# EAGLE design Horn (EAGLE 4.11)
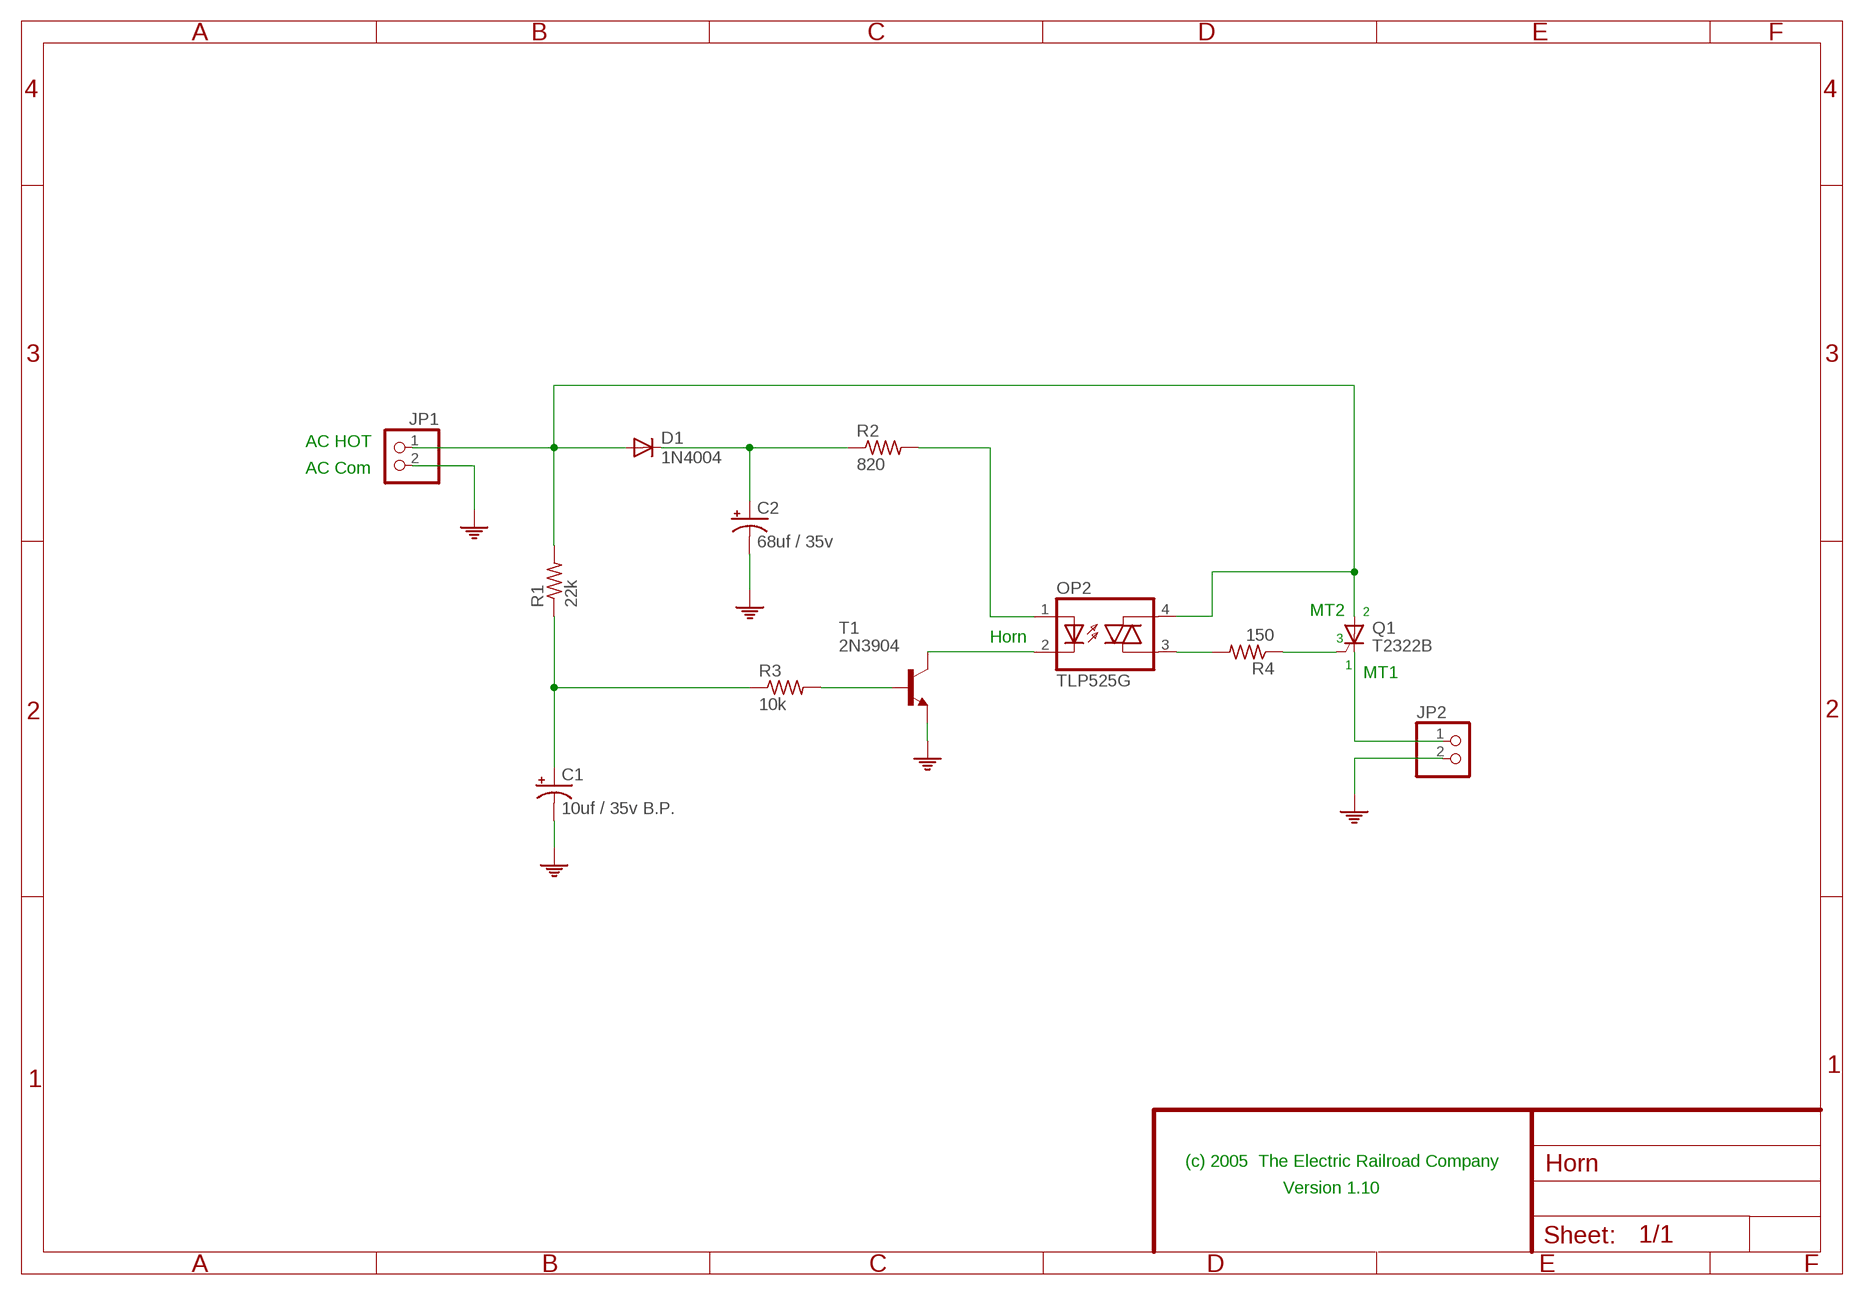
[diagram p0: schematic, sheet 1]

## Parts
C1  10uf / 35v B.P.  CPOL-USE2.5-6  [E2,5-6]
C2  68uf / 35v  CPOL-USE2.5-7  [E2,5-7]
D1  1N4004  DIODE-D-2.5  [D-2.5]
JP1  PINHD-1X2  [1X02]
JP2  PINHD-1X2  [1X02]
OP2  TLP525G  IL420  [DIL04]
Q1  T2322B  BT148  [SOT82S]
R1  22k  R-US_0204/2V  [0204V]
R2  820  R-US_0204/2V  [0204V]
R3  10k  R-US_0204/2V  [0204V]
R4  150  R-US_0204/2V  [0204V]
T1  2N3904  [TO92]

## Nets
N$2 [P24]: D1.A JP1.1 OP2.4(A2) Q1.A R1.2
N$3: OP2.1(A) R2.2
N$7: C1.+ R1.1 R3.1
N$8: R3.2 T1.2(B)
N$9: Q1.G R4.1
N$10: OP2.2(C) T1.1(C)
N$14: C2.+ D1.C R2.1
N$17: OP2.3(A1) R4.2
N$20 [P24]: JP2.1 Q1.C
PE [P24]: C1.- C2.- JP1.2 JP2.2 T1.3(E)

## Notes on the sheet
- AC HOT
- AC Com
- MT2 | 2
- Horn | 3
- 1
- MT1
- (c) 2005  The Electric Railroad Company
- Version 1.10

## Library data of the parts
C1 C2 = rcl:CPOL-US: POLARIZED CAPACITOR, American symbol
D1 = diode:DIODE-: DIODE
JP1 JP2 = pinhead:PINHD-1X2: PIN HEADER
OP2 = optocoupler-jz:IL420: SIEMENS OPTO COUPLER
Q1 = triac:BT148: THYRISTOR
R1-R4 = rcl:R-US_: RESISTOR, American symbol
T1 = transistor:2N3904: NPN TRANSISTOR

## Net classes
1 P24: width 0.61 mm, drill 0.508 mm, clearance 0.61 mm

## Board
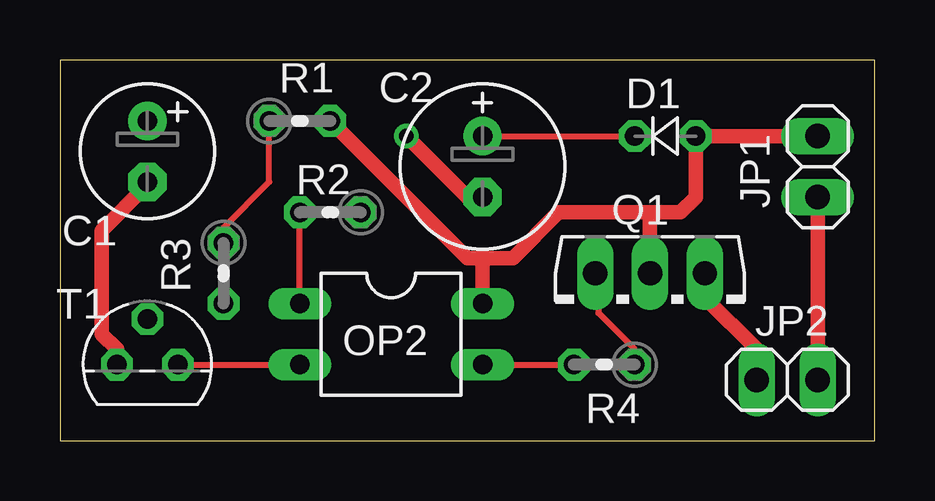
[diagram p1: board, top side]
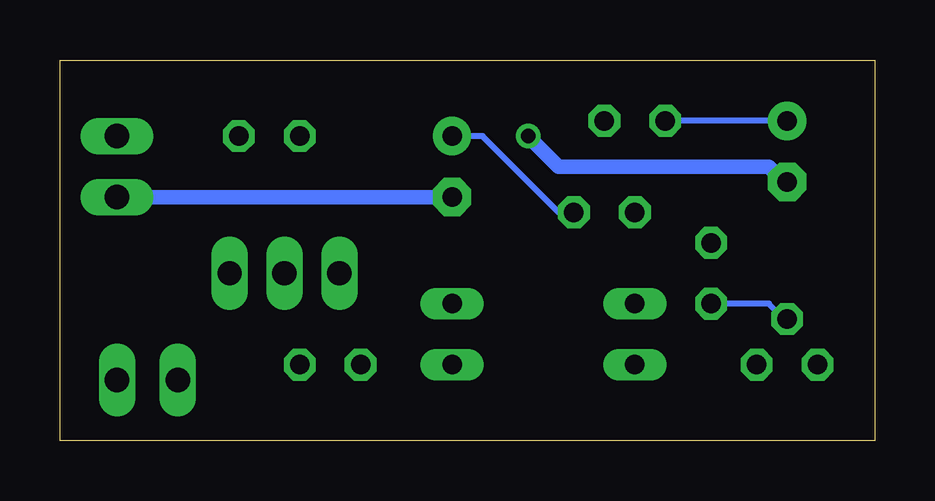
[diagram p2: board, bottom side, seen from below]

Size 33.96 x 15.87 mm. Coordinates in mm from the lower left corner, seen from the top.
Outline: 0,0 33.96,0 33.96,15.87 0,15.87 0,0
Copper layers (1*16): Top 0.035mm / dielectric 1.5mm / Bottom 0.035mm
Design rules "default": minimum track width 10mil, minimum drill 24mil, track to track 8mil, track to pad 8mil, pad to pad 8mil, via to via 8mil, smd to smd 8mil, copper to edge 20mil, drill to drill 8mil, minimum pad ring 10mil, minimum via ring 8mil, stop-mask expansion 4mil, vias tented up to drill 0mil, thermal gap 10mil

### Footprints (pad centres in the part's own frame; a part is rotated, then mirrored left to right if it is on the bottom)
E2,5-6 = drill 0.813 pad 1.6 round: + -1.27,0 | drill 0.813 pad 1.6 octagon: - 1.27,0
E2,5-7 = drill 0.813 pad 1.6 round: + -1.27,0 | drill 0.813 pad 1.6 octagon: - 1.27,0
D-2.5 = drill 0.813 octagon: A 1.27,0; C -1.27,0
1X02 = drill 1.016 long: 1 -1.27,0; 2 1.27,0
DIL04 = drill 0.813 long: 1 -1.27,-3.81; 2 1.27,-3.81; 3 1.27,3.81; 4 -1.27,3.81
SOT82S = drill 1.016 long: A 0,-1.27; C -2.286,-1.27; G 2.286,-1.27
0204V = drill 0.813 octagon: 1 -1.27,0; 2 1.27,0
TO92 = drill 0.813 octagon: 1 1.27,0; 2 0,1.905; 3 -1.27,0

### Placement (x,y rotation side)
C1  3.65,12.06 270 top
C2  17.62,11.43 270 top
D1  25.23,12.7 0 top
JP1  31.59,11.43 270 top
JP2  30.32,2.54 0 top
OP2  13.81,4.44 270 top
Q1  24.6,5.71 180 top
R1  10,13.33 0 top
R2  11.27,9.52 180 top
R3  6.82,6.98 270 top
R4  22.7,3.17 180 top
T1  3.65,3.17 0 top

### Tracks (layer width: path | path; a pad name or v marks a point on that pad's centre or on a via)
N$2
  Top 0.61: 17.62,7.62 16.98,7.62 R1.2 | JP1.1 D1.A 26.51,10.16 25.87,9.52 24.6,9.52 | 24.6,9.52 20.79,9.52 18.89,7.62 17.62,7.62 | OP2.4 17.62,7.62 | 24.6,9.52 Q1.A
N$3
  Top 0.254: OP2.1 R2.2
N$7
  Top 0.254: R3.1 6.82,8.89 8.73,10.79 R1.1
  Bottom 0.254: C1.+ R1.1
N$8
  Bottom 0.254: T1.2 3.77,5.08 4.41,5.71 R3.2
N$9
  Top 0.254: R4.1 23.96,3.8 22.44,5.33 22.44,6.47 Q1.G
N$10
  Top 0.254: T1.1 OP2.2
N$14
  Top 0.254: C2.+ D1.C
  Bottom 0.254: R2.1 13.17,9.52 16.35,12.7 C2.+
N$17
  Top 0.254: OP2.3 R4.2
N$20
  Top 0.61: JP2.1 29.05,3.8 26.89,5.96 Q1.C
PE  (via drill 0.61)
  Top 0.61: T1.3 2.38,3.8 1.74,4.44 1.74,8.76 3.65,10.66 C1.- | JP1.2 JP2.2 | v14.44,12.7 16.98,10.16 C2.-
  Bottom 0.61: C2.- JP1.2 | v14.44,12.7 13.17,11.43 4.41,11.43 3.77,10.79 C1.-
